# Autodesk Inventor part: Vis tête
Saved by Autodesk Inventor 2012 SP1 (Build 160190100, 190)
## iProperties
Created: 2014-12
Part Number: Vis tête
Material: Default
Document SubType Name: Modeling
Designer: Bruno
Density: 1 g/cm^3
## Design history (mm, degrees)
node "Vis tête1"
node "Vis tête"
node "Base1"
